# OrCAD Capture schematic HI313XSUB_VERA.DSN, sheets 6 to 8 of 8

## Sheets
6 PAGE7_Hi3130V200: size Custom
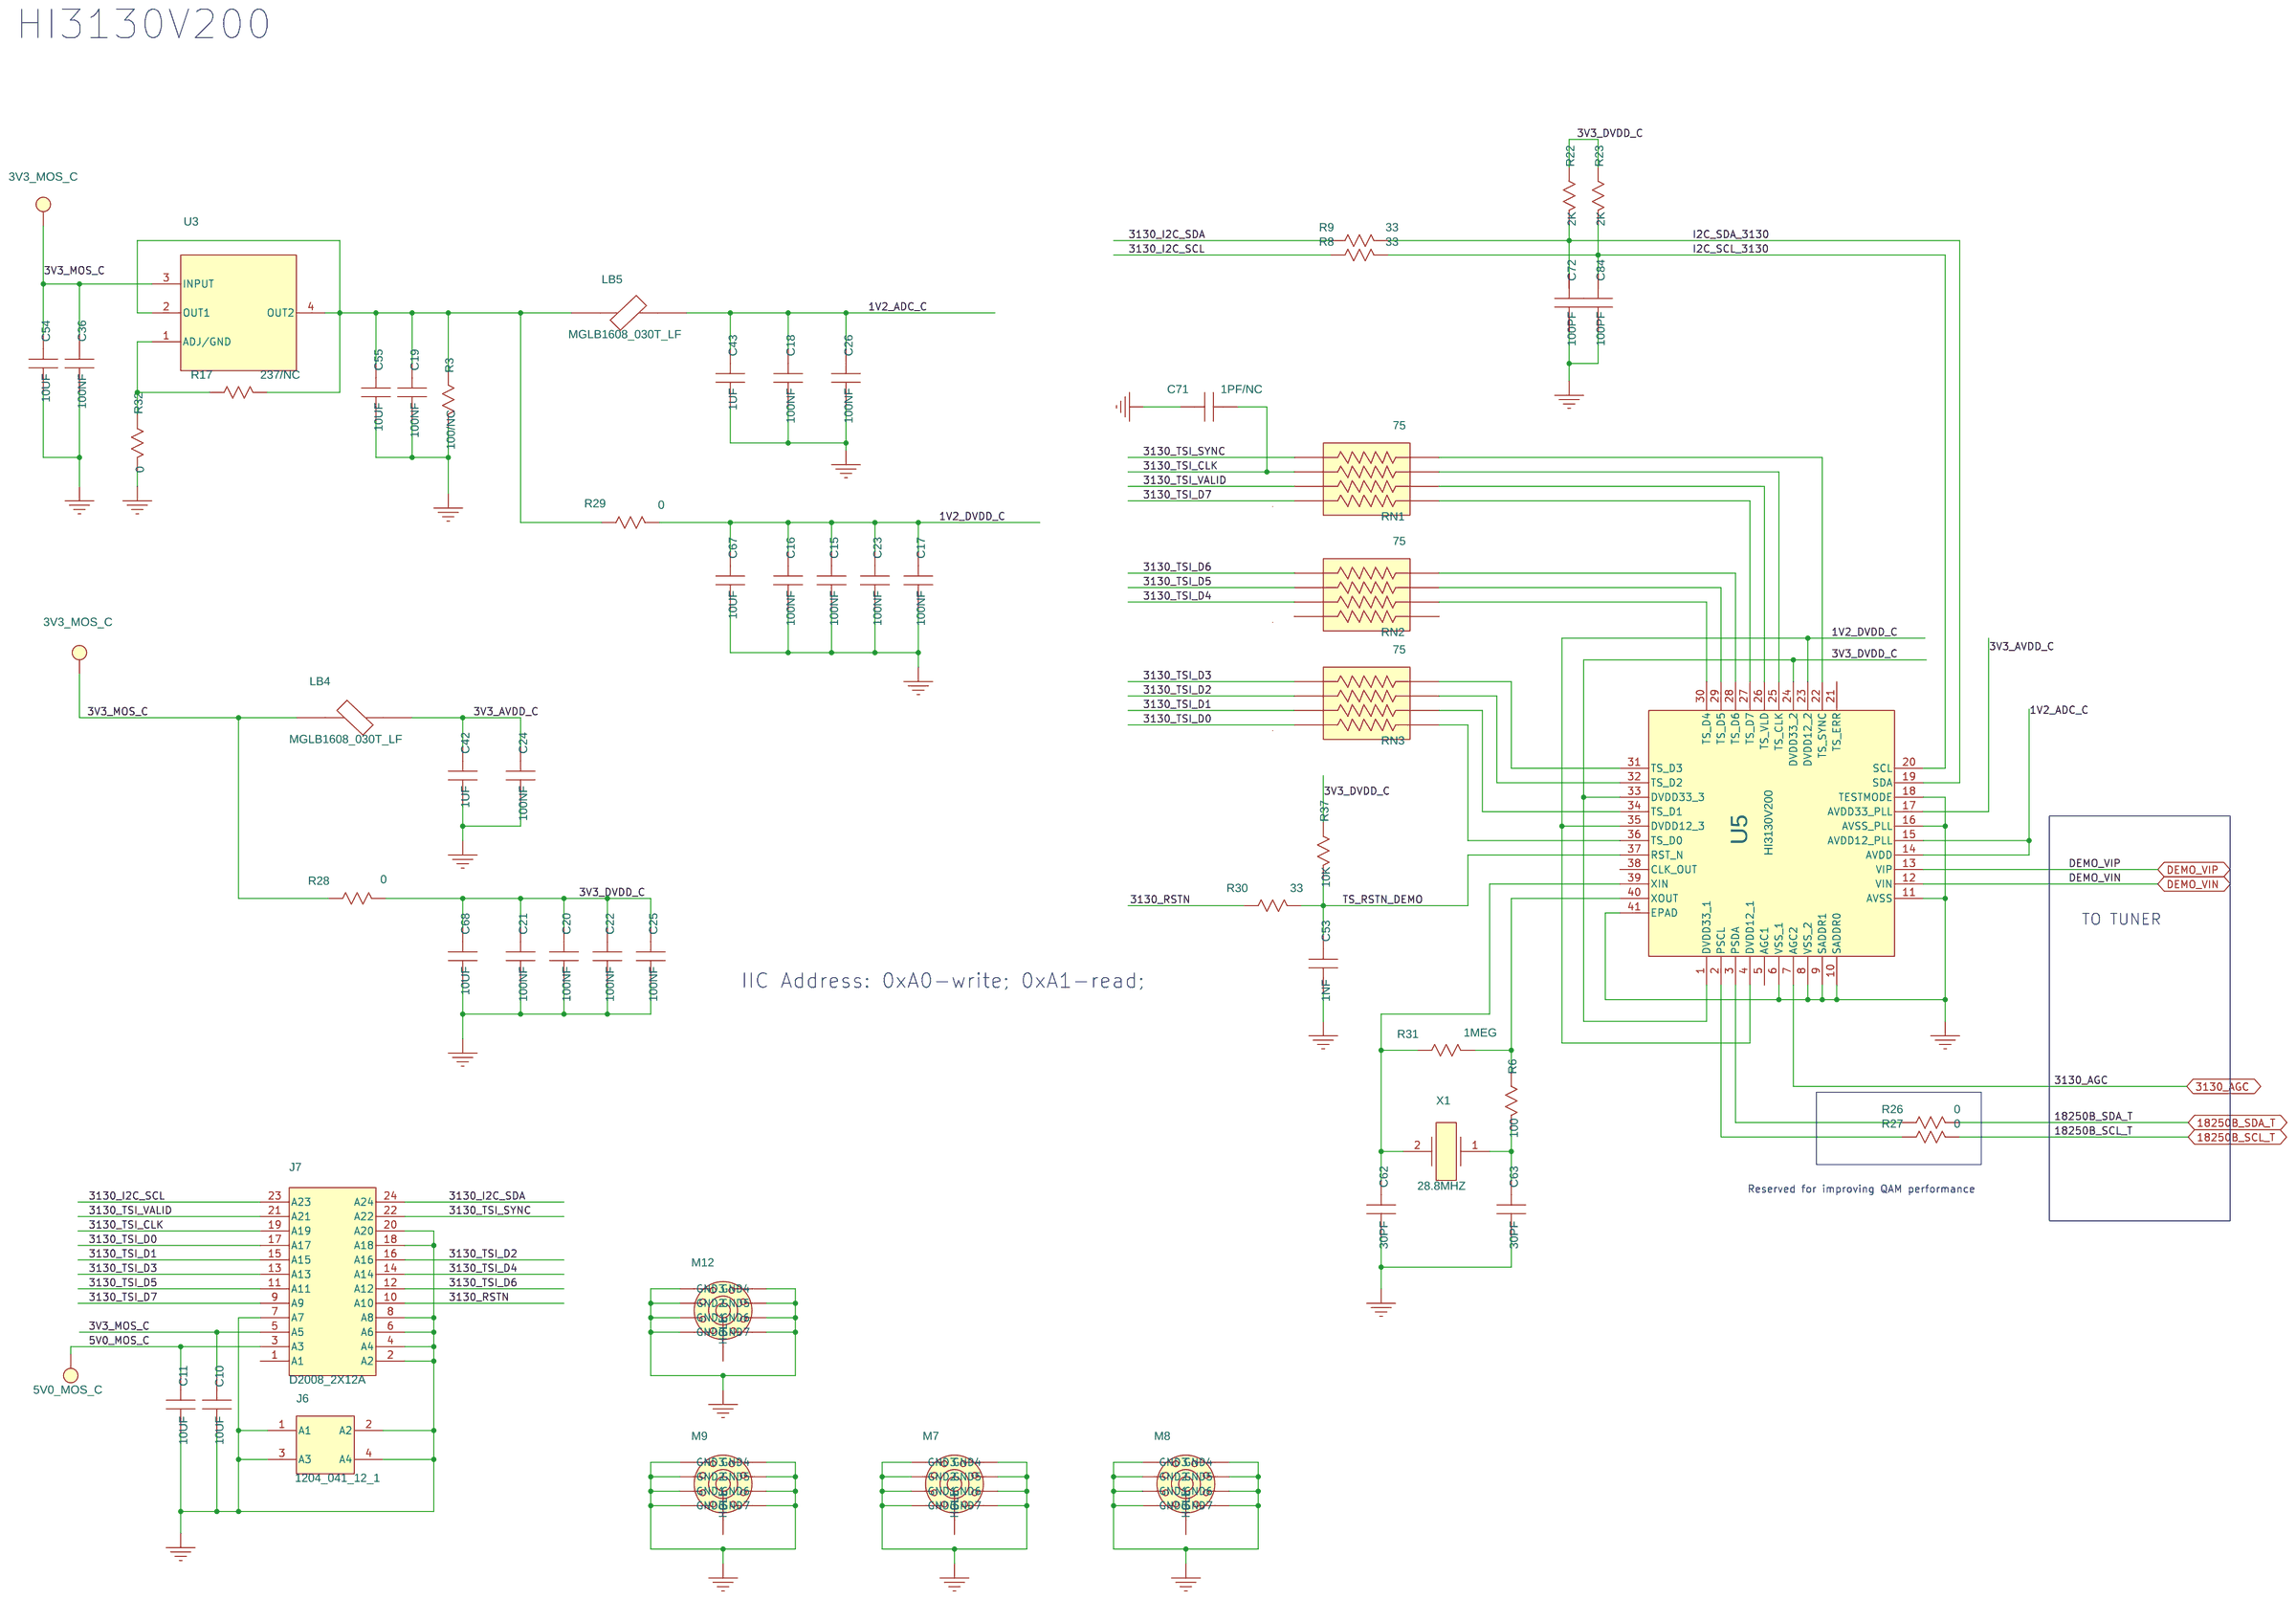
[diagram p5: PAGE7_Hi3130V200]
7 PAGE8_TDA18250B: size Custom
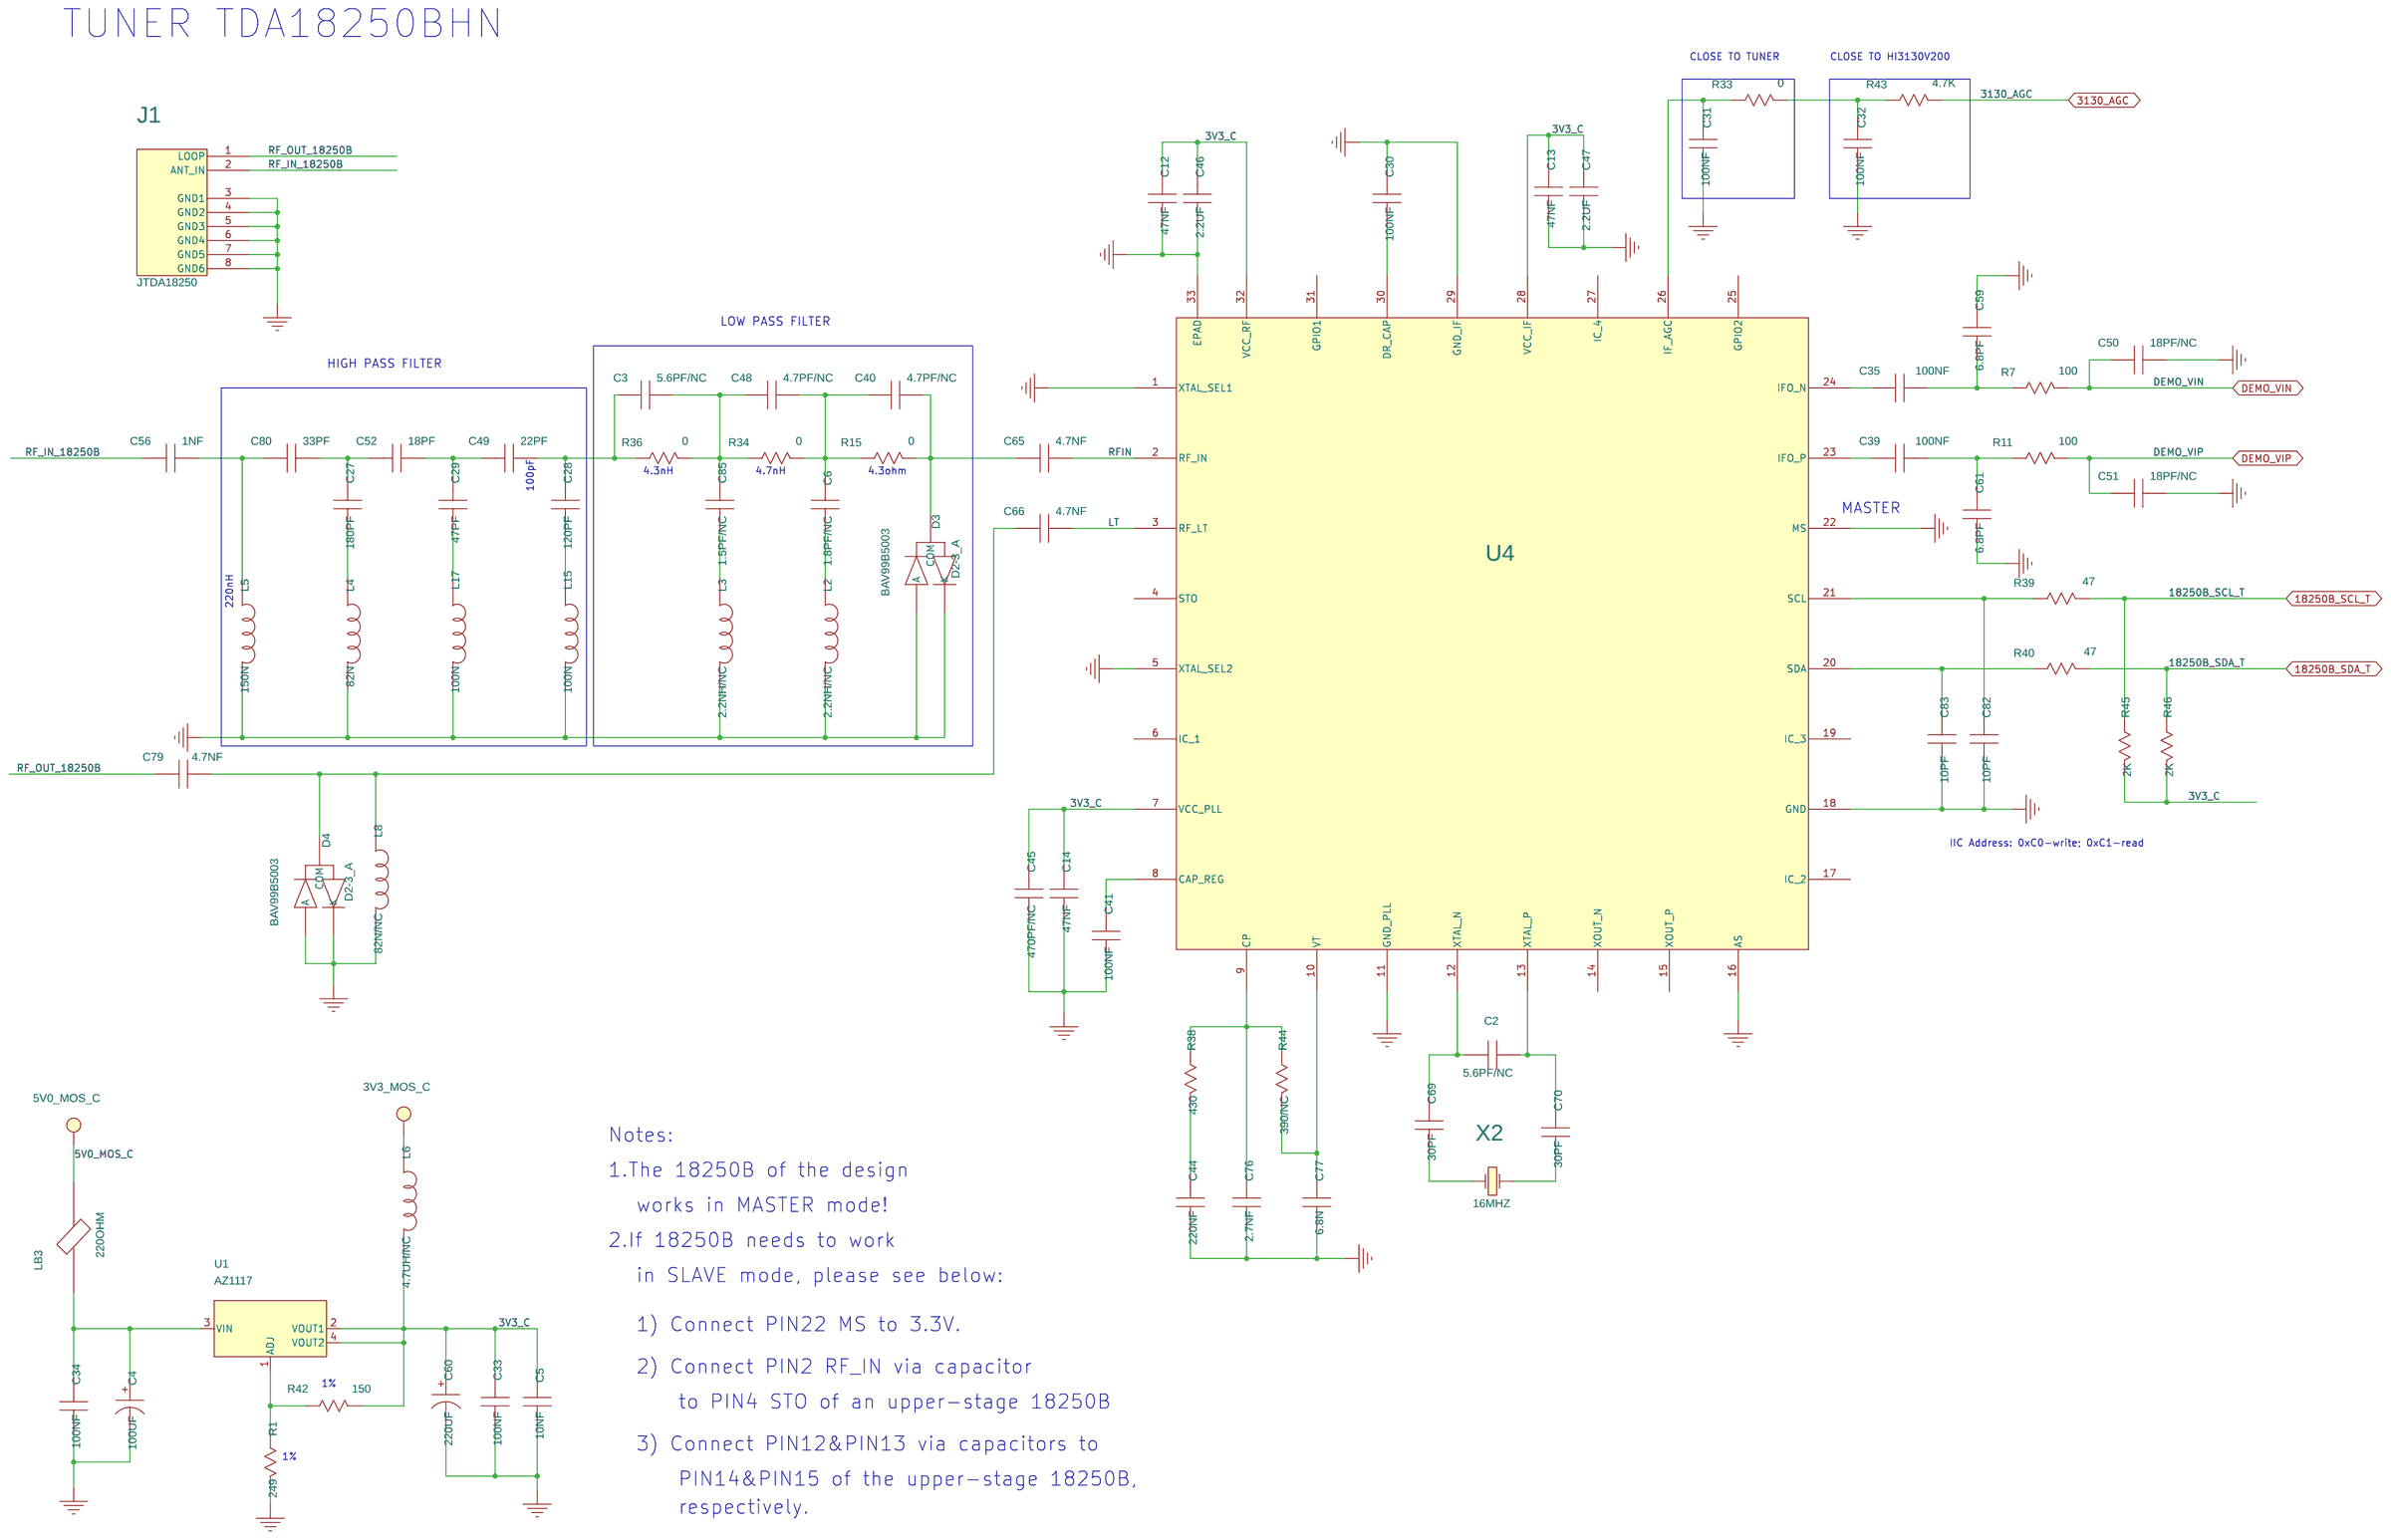
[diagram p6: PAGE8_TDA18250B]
8 PAGE6_MXL603//MXL608: size Custom
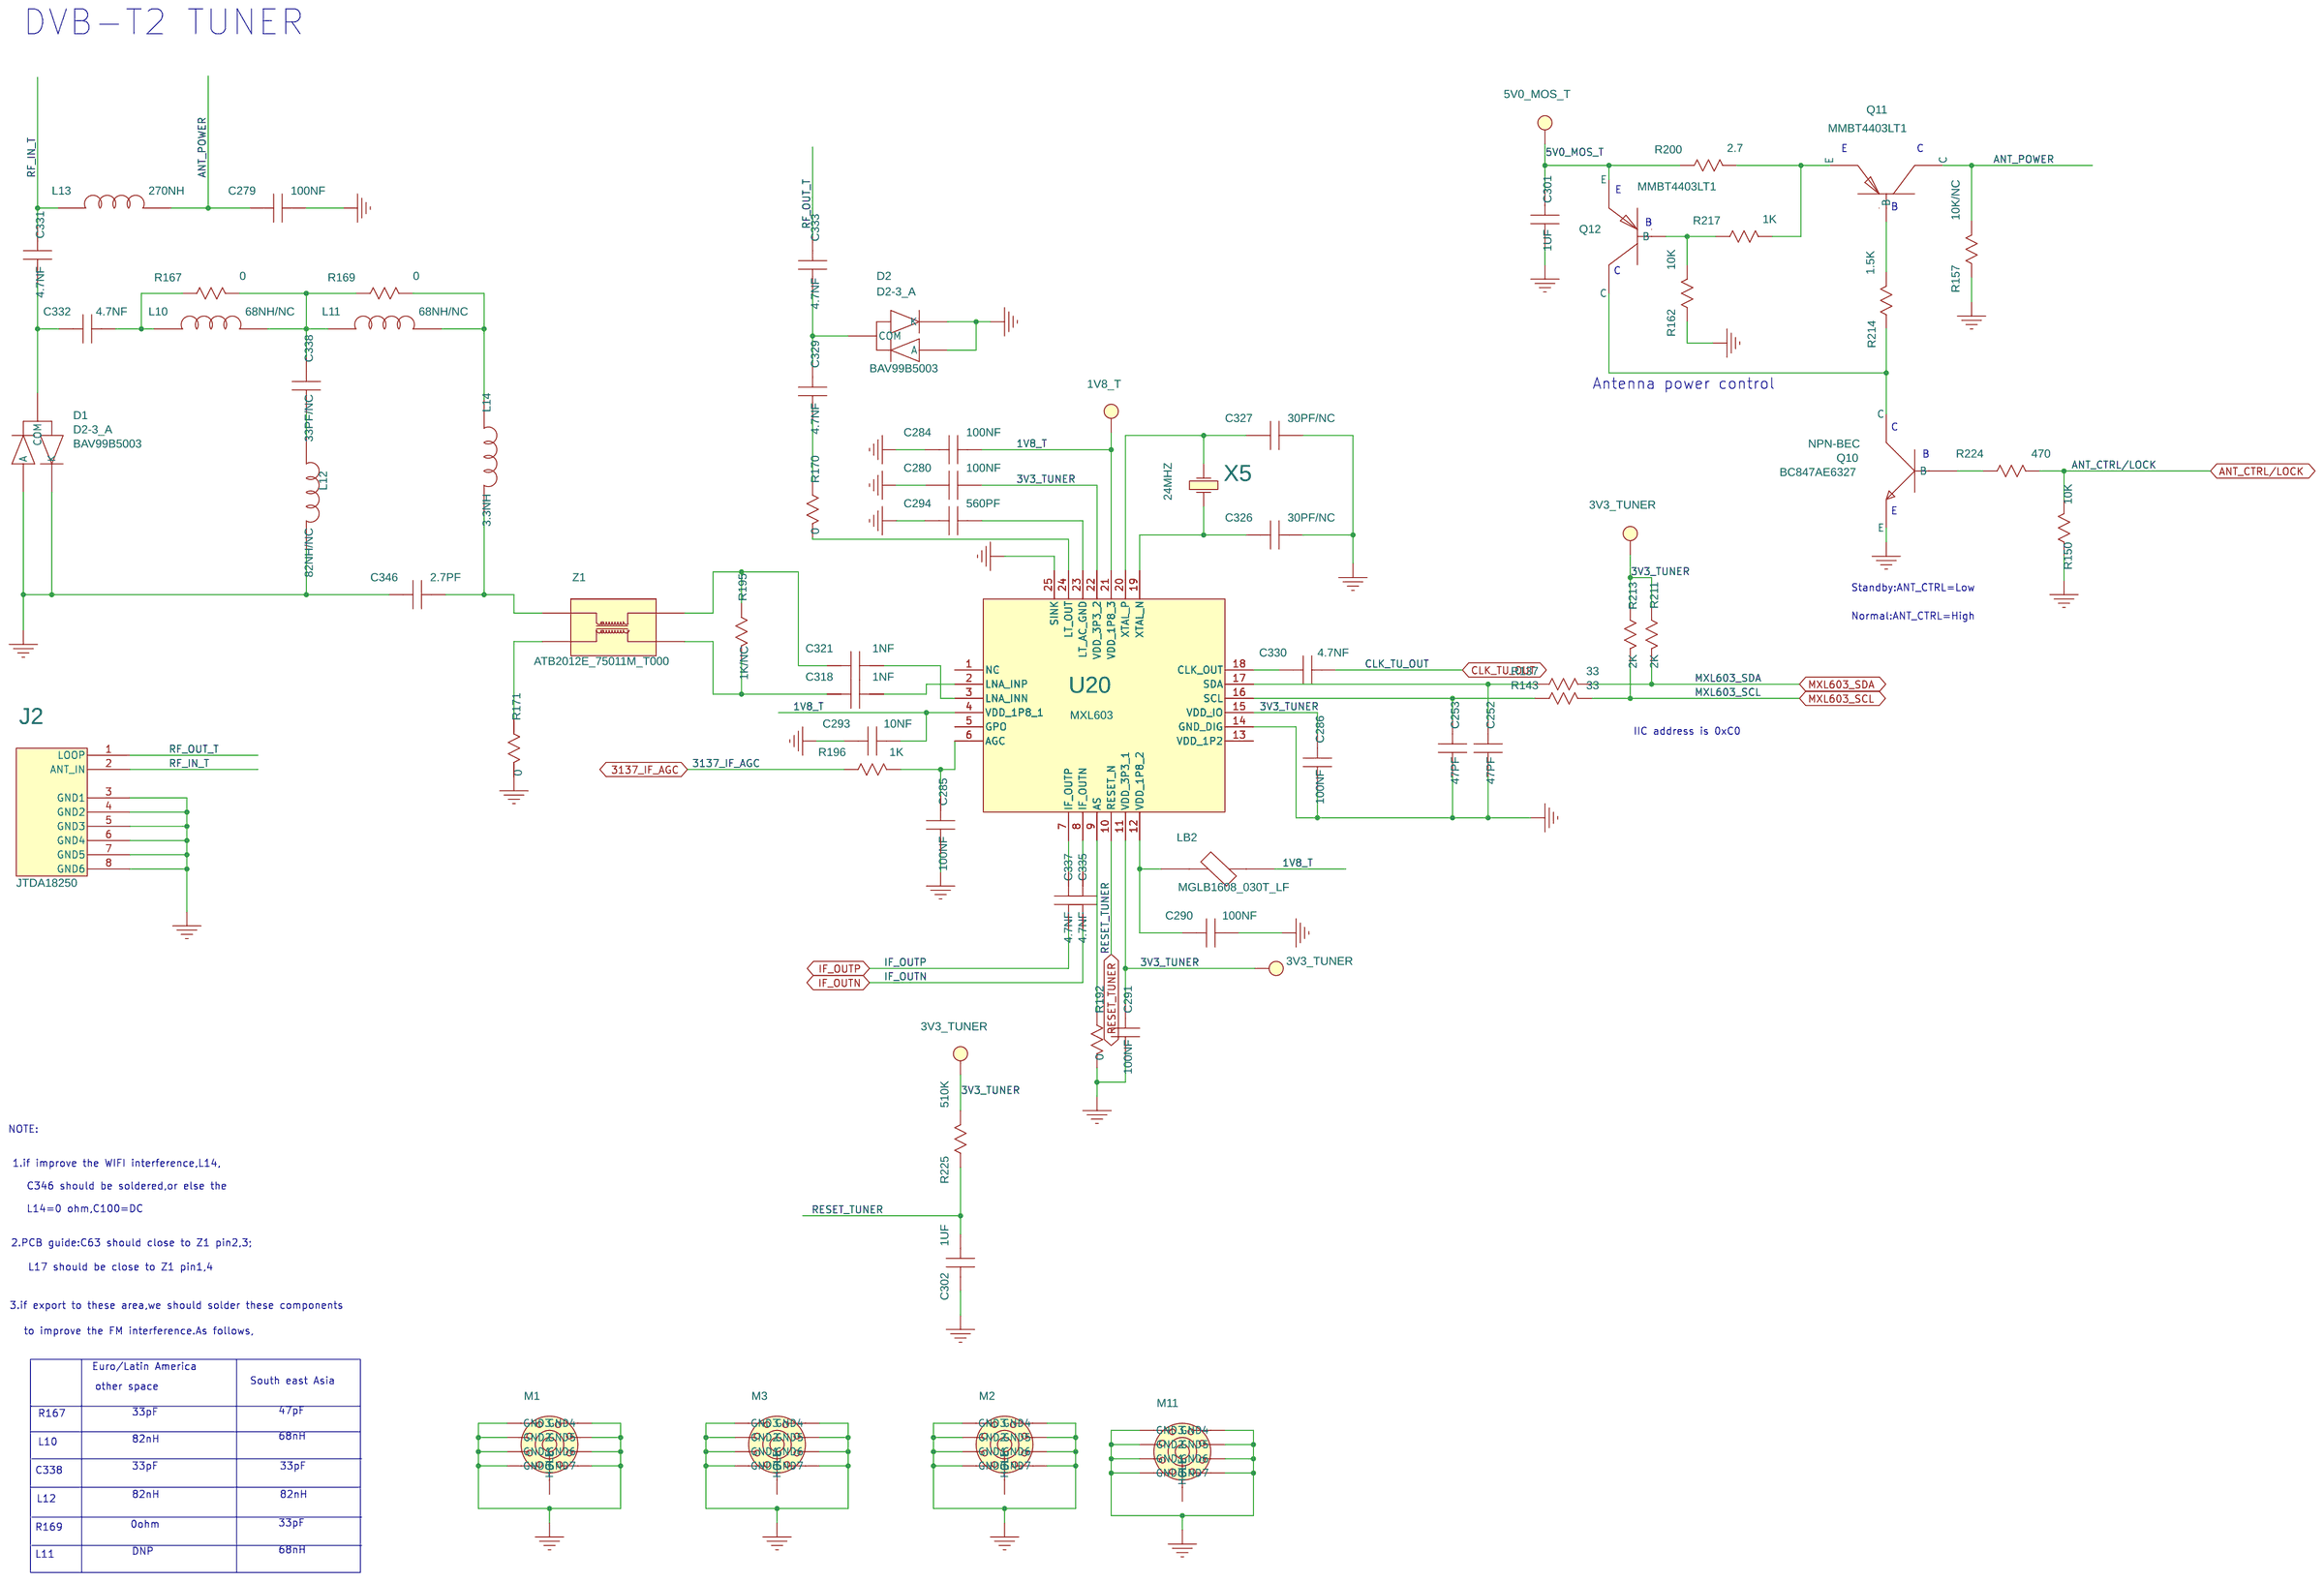
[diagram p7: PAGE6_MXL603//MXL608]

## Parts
sheet PAGE6_MXL603//MXL608
C252  47PF  [SC0402]
C253  47PF  [SC0402]
C279  100NF  [SC0402]
C280  100NF  [SC0402]
C284  100NF  [SC0402]
C285  100NF  [SC0402]
C286  100NF  [SC0402]
C290  100NF  [SC0402]
C291  100NF  [SC0402]
C293  10NF  [SC0402]
C294  560PF  [SC0603]
C301  1UF  [SC0603]
C302  1UF  [SC0603]
C318  1NF  [SC0603]
C321  1NF  [SC0603]
C326  30PF/NC  [SC0402]
C327  30PF/NC  [SC0402]
C329  4.7NF  [SC0402]
C330  4.7NF  [SC0402]
C331  4.7NF  [SC0402]
C332  4.7NF  [SC0402]
C333  4.7NF  [SC0402]
C335  4.7NF  [SC0402]
C337  4.7NF  [SC0402]
C338  33PF/NC  [SC0402]
C346  2.7PF  [SC0402]
D1  D2-3_A  [SOT23]
D2  D2-3_A  [SOT23]
J2  JTDA18250  [JTDA18250]
L10  68NH/NC  [SL0402]
L11  68NH/NC  [SL0402]
L12  82NH/NC  [SL0402]
L13  270NH  [SL0603A]
L14  3.3NH  [SL0402]
LB2  LB  [SL0603]
M1  HOLE-8STARS  [HOLE138-8STAR]
M2  HOLE-8STARS  [HOLE138-8STAR]
M3  HOLE-8STARS  [HOLE138-8STAR]
M11  HOLE-8STARS  [HOLE138-8STAR]
Q10  NPN-BEC  [SOT23]
Q11  PNP-BEC  [SOT23]
Q12  PNP-BEC  [SOT23]
R137  33  [SR0402]
R143  33  [SR0402]
R150  10K  [SR0603]
R157  10K/NC  [SR0603]
R162  10K  [SR0603]
R167  0  [SR0402]
R169  0  [SR0402]
R170  0  [SR0402]
R171  0  [SR0402]
R192  0  [SR0402]
R195  1K/NC  [SR0402]
R196  1K  [SR0402]
R200  2.7  [SR1206]
R211  2K  [SR0402]
R213  2K  [SR0402]
R214  1.5K  [SR0603]
R217  1K  [SR0603]
R224  470  [SR0603]
R225  510K  [SR0603]
U20  MXL603  [MLF24B-050-0404L]
X5  24MHZ  [SX2-1205]
Z1  TCM1005-900-2P-T  [RF4-TDK-ATB2012E]
sheet PAGE7_Hi3130V200
C10  10UF  [SC0805]
C11  10UF  [SC0805]
C15  100NF  [SC0402]
C16  100NF  [SC0402]
C17  100NF  [SC0402]
C18  100NF  [SC0402]
C19  100NF  [SC0402]
C20  100NF  [SC0402]
C21  100NF  [SC0402]
C22  100NF  [SC0402]
C23  100NF  [SC0402]
C24  100NF  [SC0402]
C25  100NF  [SC0402]
C26  100NF  [SC0402]
C36  100NF  [SC0603]
C42  1UF  [SC0603]
C43  1UF  [SC0603]
C53  1NF  [SC0402]
C54  10UF  [SC0805]
C55  10UF  [SC0805]
C62  30PF  [SC0402]
C63  30PF  [SC0402]
C67  10UF  [SC0603]
C68  10UF  [SC0603]
C71  1PF/NC  [SC0402]
C72  100PF  [SC0402]
C84  100PF  [SC0402]
J6  HEAD2X2  [HEAD0202-RM]
J7  WBC2X12  [HEAD0212-RM-SUB]
LB4  LB  [SL0603]
LB5  LB  [SL0603]
M7  HOLE-8STARS  [HOLE138-8STAR]
M8  HOLE-8STARS  [HOLE138-8STAR]
M9  HOLE-8STARS  [HOLE138-8STAR]
M12  HOLE-8STARS  [HOLE138-8STAR]
R3  100/NC  [SR0402]
R6  100  [SR0402]
R8  33  [SR0402]
R9  33  [SR0402]
R17  237/NC  [SR0402]
R22  2K  [SR0402]
R23  2K  [SR0402]
R26  0  [SR0603]
R27  0  [SR0603]
R28  0  [SR0603]
R29  0  [SR0603]
R30  33  [SR0402]
R31  1MEG  [SR0402]
R32  0  [SR0402]
R37  10K  [SR0402]
RN1  75  [SRN8-0804]
RN2  75  [SRN8-0804]
RN3  75  [SRN8-0804]
U3  TLV1117CKTPR  [SOT223A]
U5  HI3130V200  [MLF40B-040-0505L]
X1  28.8MHZ  [XTAL2-200A]
sheet PAGE8_TDA18250B
C2  5.6PF/NC  [SC0402]
C3  5.6PF/NC  [SC0402]
C4  100UF  [CAPC2-79-217]
C5  10NF  [HSC0402]
C6  1.8PF/NC  [SC0402]
C12  47NF  [SC0402]
C13  47NF  [SC0402]
C14  47NF  [SC0402]
C27  180PF  [SC0402]
C28  120PF  [SC0402]
C29  47PF  [SC0402]
C30  100NF  [SC0402]
C31  100NF  [SC0402]
C32  100NF  [SC0402]
C33  100NF  [SC0402]
C34  100NF  [SC0402]
C35  100NF  [SC0402]
C39  100NF  [SC0402]
C40  4.7PF/NC  [SC0402]
C41  100NF  [SC0402]
C44  220NF  [SC0402]
C45  470PF/NC  [SC0402]
C46  2.2UF  [SC0603]
C47  2.2UF  [SC0603]
C48  4.7PF/NC  [SC0402]
C49  22PF  [SC0402]
C50  18PF/NC  [SC0402]
C51  18PF/NC  [SC0402]
C52  18PF  [SC0402]
C56  1NF  [SC0402]
C59  6.8PF  [SC0402]
C60  220UF  [CAPC2-100-250]
C61  6.8PF  [SC0402]
C65  4.7NF  [SC0402]
C66  4.7NF  [SC0402]
C69  30PF  [SC0402]
C70  30PF  [SC0402]
C76  2.7NF  [SC0402]
C77  6.8N  [HSC0402-TA]
C79  4.7NF  [SC0402]
C80  33PF  [SC0402]
C82  10PF  [SC0402]
C83  10PF  [SC0402]
C85  1.5PF/NC  [SC0402]
D3  D2-3_A  [SOT23]
D4  D2-3_A  [SOT23]
J1  JTDA18250  [JTDA18250]
L2  2.2NH/NC  [SL0402]
L3  2.2NH/NC  [SL0402]
L4  82N  [HSL0402-TC]
L5  150N  [HSL0402]
L6  4.7UH/NC  [HSL1007]
L8  82N/NC  [HSL0402-TC]
L15  100N  [HSL0402-TC]
L17  100N  [HSL0402-TC]
LB3  220OHM  [SL0805]
R1  249  [SR0603]
R7  100  [SR0402]
R11  100  [SR0402]
R15  0  [SR0402]
R33  0  [SR0402]
R34  0  [SR0402]
R36  0  [SR0402]
R38  430  [SR0402]
R39  47  [SR0402]
R40  47  [SR0402]
R42  150  [SR0402]
R43  4.7K  [SR0402]
R44  390/NC  [SR0402]
R45  2K  [SR0402]
R46  2K  [SR0402]
U1  LM317EMP  [SOT223A]
U4  TDA18250B  [HVQFN32]
X2  16MHZ  [SX2-1205]

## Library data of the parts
C29 C252 C253 = C: %182%%238%%182%%168%%185%%164%%215%%247%%181%%231%%209%%185%(V): 50; %195%%232%%202%%246%: SMD陶瓷电容-50V-0.047NF-+/-5%-NP0-0402; %208%%161%%192%%224%%195%%251%%179%%198%: SMD陶瓷电容; CODE: 8070549; COMPONENT_HIGH_MAX: 0.55MM; DEVICE: C0402C470J5GAC_7867
C279 C280 C284-C286 C290 C291 = C: %182%%238%%182%%168%%185%%164%%215%%247%%181%%231%%209%%185%(V): 10; %195%%232%%202%%246%: SMD陶瓷电容-10V-100NF-+/-10%-X5R-0402; %208%%161%%192%%224%%195%%251%%179%%198%: SMD陶瓷电容; CODE: 8070561; COMPONENT_HIGH_MAX: 0.55MM; DEVICE: C0402C104K8PAC_7867
C293 = C: %182%%238%%182%%168%%185%%164%%215%%247%%181%%231%%209%%185%(V): 16; %195%%232%%202%%246%: SMD陶瓷电容-16V-10NF-+/-10%-X7R-0402-BT,TS16949; %208%%161%%192%%224%%195%%251%%179%%198%: SMD陶瓷电容; CODE: 8070449; COMPONENT_HIGH_MAX: 0.56MM; DEVICE: GRM155R71C103KA01D
C294 = C: %182%%238%%182%%168%%185%%164%%215%%247%%181%%231%%209%%185%(V): 50; %195%%232%%202%%246%: SMD陶瓷电容-50V-0.56NF-+/-5%-NPO-0603; %208%%161%%192%%224%%195%%251%%179%%198%: SMD陶瓷电容; CODE: 8070414; COMPONENT_HIGH_MAX: 0.9MM; DEVICE: CC0603JRNPO9BN561
C301 = C: %182%%238%%182%%168%%185%%164%%215%%247%%181%%231%%209%%185%(V): 6.3; %195%%232%%202%%246%: SMD陶瓷电容-6.3V-1000NF-+/-10%-X5R-0603; %208%%161%%192%%224%%195%%251%%179%%198%: SMD陶瓷电容; CODE: 8070562; DEVICE: CC0603KRX5R5BB105
C302 = C: %182%%238%%182%%168%%185%%164%%215%%247%%181%%231%%209%%185%(V): 6.3; %195%%232%%202%%246%: SMD陶瓷电容-6.3V-1000NF-+/-10%-X5R-0603; %208%%161%%192%%224%%195%%251%%179%%198%: SMD陶瓷电容; CODE: 8070562; COMPONENT_HIGH_MAX: 0.9MM; DEVICE: CC0603KRX5R5BB105
C318 C321 = C: %182%%238%%182%%168%%185%%164%%215%%247%%181%%231%%209%%185%(V): 50; %195%%232%%202%%246%: SMD陶瓷电容-50V-1NF-+/-10%-X7R-0603; %208%%161%%192%%224%%195%%251%%179%%198%: SMD陶瓷电容; CODE: 8070249; COMPONENT_HIGH_MAX: 0.9MM; DEVICE: 06035C102KAT2A
C62 C63 C69 C70 C326 C327 = C: %182%%238%%182%%168%%185%%164%%215%%247%%181%%231%%209%%185%(V): 50; %195%%232%%202%%246%: SMD陶瓷电容-50V-0.03NF-+/-5%-NPO-0402; %208%%161%%192%%224%%195%%251%%179%%198%: SMD陶瓷电容; CODE: 8070604; COMPONENT_HIGH_MAX: 0.55MM; DEVICE: GRM1555C1H300J
C65 C66 C79 C329-C333 C335 C337 = C: %182%%238%%182%%168%%185%%164%%215%%247%%181%%231%%209%%185%(V): 50; %195%%232%%202%%246%: SMD陶瓷电容-50V-4.7NF-+/-10%-X7R-0402; %208%%161%%192%%224%%195%%251%%179%%198%: SMD陶瓷电容; CODE: 8070559; COMPONENT_HIGH_MAX: 0.55MM; DEVICE: UMK105BJ472KV_F
C80 C338 = C: %182%%238%%182%%168%%185%%164%%215%%247%%181%%231%%209%%185%(V): 50; %195%%232%%202%%246%: SMD陶瓷电容-50V-0.033NF-+/-5%-NP0-0402-BT; %208%%161%%192%%224%%195%%251%%179%%198%: SMD陶瓷电容; CODE: 8070547; COMPONENT_HIGH_MAX: 0.55MM; DEVICE: CC0402JRNPO9BN330
C346 = C: %182%%238%%182%%168%%185%%164%%215%%247%%181%%231%%209%%185%(V): 50; %195%%232%%202%%246%: SMD陶瓷电容-50V-0.0027NF-+/-0.25PF-NPO-0402; %208%%161%%192%%224%%195%%251%%179%%198%: SMD陶瓷电容; CODE: 8070590; COMPONENT_HIGH_MAX: 0.55MM; DEVICE: GRM1555C1H2R7CZ01D
D1 D2 = D2-3_A: %195%%232%%202%%246%: 开关二极管-70V-200MA-1.25V-6NS-串联-SOT-23-2 FIT; CODE: 15010042; DEVICE: BAV99B5003
J1 J2 = JTDA18250
L10 L11 = L: %195%%232%%202%%246%: 贴片电感器-0.068UH-5%-1.7OHM-0402; %208%%161%%192%%224%%195%%251%%179%%198%: 贴片电感器; CODE: 10031125; COMPONENT_HIGH_MAX: 0.55MM; DEVICE: MGCI1005T68NJT_LF
L12 = L: %195%%232%%202%%246%: 贴片电感器-0.082UH-5%-1.9OHM-0402; %208%%161%%192%%224%%195%%251%%179%%198%: 贴片电感器; CODE: 10031126; COMPONENT_HIGH_MAX: 0.55MM; DEVICE: LL1005_FH82NJ
L13 = L: %195%%232%%202%%246%: 贴片电感器-0.27UH-2%-2.3OHM-15-0603; %208%%161%%192%%224%%195%%251%%179%%198%: 贴片电感器; CODE: 10031131; COMPONENT_HIGH_MAX: 1.02MM; DEVICE: 0603CS_R27XJLW
L14 = L: %195%%232%%202%%246%: 贴片电感器-0.0033UH-0.3NH-0.19OHM-0402; %208%%161%%192%%224%%195%%251%%179%%198%: 贴片电感器; CODE: 10031117; COMPONENT_HIGH_MAX: 0.55MM; DEVICE: LL1005_FHL3N3S
LB2 LB4 LB5 = LB: %195%%232%%202%%246%: EMI磁珠-30OHM-0.05OHM-0.4A-0603-; %208%%161%%192%%224%%195%%251%%179%%198%: EMI磁珠; CODE: 10070003; COMPONENT_HIGH_MAX: 0.95MM; DEVICE: MGLB1608_030T_LF
M1-M3 M7-M9 M11 M12 = HOLE-8STARS: %195%%232%%202%%246%: M3螺钉(推荐使用)，对应138MIL星月孔，适用于过波峰焊设计。; DEVICE: 138MIL_STAR_HOLE_APPLY_TO_M3
Q10 = NPN-BEC_0: %195%%232%%202%%246%: 三极管-NPN-45V-100MA-225MW-200MV@100MA-SOT-23-180@2MA; %208%%161%%192%%224%%195%%251%%179%%198%: 三极管; CODE: 15050206; DEVICE: BC847AE6327
Q11 Q12 = PNP-BEC_0: %195%%232%%202%%246%: 三极管-PNP-40V-600MA-350MW-750MV@500MA，400MV@150MA-SOT-23-100@150MA; %208%%161%%192%%224%%195%%251%%179%%198%: 三极管; CODE: 15050072; DEVICE: MMBT4403LT1
R30 R137 R143 = R: %182%%238%%182%%168%%185%%166%%194%%202%(W): 0.06; %195%%232%%202%%246%: 片式厚膜电阻器-0.0625W-33OHM-+/-1%-0402; %208%%161%%192%%224%%195%%251%%179%%198%: 片式厚膜电阻器; %215%%232%%214%%181%%212%%202%%208%%237%%198%%171%%178%%238%: +/-1%; CODE: 7090836; COMPONENT_HIGH_MAX: 0.4MM; DEVICE: RC0402FR_0733RL
R150 R157 R162 = R: %182%%238%%182%%168%%185%%166%%194%%202%(W): 0.1; %195%%232%%202%%246%: 片式厚膜电阻器-0.1W-10000OHM-+/-5%-0603-TS16949; %208%%161%%192%%224%%195%%251%%179%%198%: 片式厚膜电阻器; %215%%232%%214%%181%%212%%202%%208%%237%%198%%171%%178%%238%: +/-5%; CODE: 7090247; DEVICE: RC0603JR_0710K
R167 R169 = R: %182%%238%%182%%168%%185%%166%%194%%202%(W): 0.06; %195%%232%%202%%246%: 片式厚膜电阻器-0.0625W-0OHM-< 50MOHM-0402-1A-BT; %208%%161%%192%%224%%195%%251%%179%%198%: 片式厚膜电阻器; %215%%232%%214%%181%%212%%202%%208%%237%%198%%171%%178%%238%: < 50MOHM; CODE: 7090800; COMPONENT_HIGH_MAX: 0.35MM; DEVICE: RC0402JR_070R
R15 R34 R36 R170 R171 R192 = R: %182%%238%%182%%168%%185%%166%%194%%202%(W): 0.06; %195%%232%%202%%246%: 片式厚膜电阻器-0.0625W-0OHM-< 50MOHM-0402-1A-BT; %208%%161%%192%%224%%195%%251%%179%%198%: 片式厚膜电阻器; %215%%232%%214%%181%%212%%202%%208%%237%%198%%171%%178%%238%: < 50MOHM; CODE: 7090800; DEVICE: RC0402JR_070R
R195 R196 = R: %182%%238%%182%%168%%185%%166%%194%%202%(W): 0.06; %195%%232%%202%%246%: 片式厚膜电阻器-0.0625W-1000OHM-+/-5%-0402-BT; %208%%161%%192%%224%%195%%251%%179%%198%: 片式厚膜电阻器; %215%%232%%214%%181%%212%%202%%208%%237%%198%%171%%178%%238%: +/-5%; CODE: 7090809; COMPONENT_HIGH_MAX: 0.4MM; DEVICE: RC0402JR_071KL
R200 = R: %182%%238%%182%%168%%185%%166%%194%%202%(W): 0.25; %195%%232%%202%%246%: 片式厚膜电阻器-0.25W-2.7OHM-+/-1%-1206-BT; %208%%161%%192%%224%%195%%251%%179%%198%: 片式厚膜电阻器; %215%%232%%214%%181%%212%%202%%208%%237%%198%%171%%178%%238%: +/-1%; CODE: 7090724; DEVICE: RC1206FR_072R7
R211 R213 = R: %182%%238%%182%%168%%185%%166%%194%%202%(W): 0.06; %195%%232%%202%%246%: 片式厚膜电阻器-0.0625W-2000OHM-+/-1%-0402-BT; %208%%161%%192%%224%%195%%251%%179%%198%: 片式厚膜电阻器; %215%%232%%214%%181%%212%%202%%208%%237%%198%%171%%178%%238%: +/-1%; CODE: 7091354; COMPONENT_HIGH_MAX: 0.4MM; DEVICE: RC_02W2001FT
R214 = R: %182%%238%%182%%168%%185%%166%%194%%202%(W): 0.1; %195%%232%%202%%246%: 片式厚膜电阻器-0.1W-1500OHM-+/-1%-0603; %208%%161%%192%%224%%195%%251%%179%%198%: 片式厚膜电阻器; %215%%232%%214%%181%%212%%202%%208%%237%%198%%171%%178%%238%: +/-1%; CODE: 7091272; DEVICE: RK73H1JTTD1501F
R217 = R: %182%%238%%182%%168%%185%%166%%194%%202%(W): 0.1; %195%%232%%202%%246%: 片式厚膜电阻器-0.1W-1000OHM-+/-5%-0603-TS16949; %208%%161%%192%%224%%195%%251%%179%%198%: 片式厚膜电阻器; %215%%232%%214%%181%%212%%202%%208%%237%%198%%171%%178%%238%: +/-5%; CODE: 7090277; DEVICE: RC0603JR_071K
R224 = R: %182%%238%%182%%168%%185%%166%%194%%202%(W): 0.1; %195%%232%%202%%246%: 片式厚膜电阻器-0.1W-470OHM-+/-5%-0603; %208%%161%%192%%224%%195%%251%%179%%198%: 片式厚膜电阻器; %215%%232%%214%%181%%212%%202%%208%%237%%198%%171%%178%%238%: +/-5%; CODE: 7090275; DEVICE: RC0603JR_07470R
R225 = R: %182%%238%%182%%168%%185%%166%%194%%202%(W): 0.1; %195%%232%%202%%246%: 片式厚膜电阻器-0.1W-510000OHM-+/-5%-0603; %208%%161%%192%%224%%195%%251%%179%%198%: 片式厚膜电阻器; %215%%232%%214%%181%%212%%202%%208%%237%%198%%171%%178%%238%: +/-5%; CODE: 7090648; COMPONENT_HIGH_MAX: 0.5MM; DEVICE: RC0603JR_07510KL
U20 = MXL603_0
X5 = X3: %195%%232%%202%%246%: 晶体谐振器-24MHZ-20PF-+/-30PPM-40OHM-HC-49S; %208%%161%%192%%224%%195%%251%%179%%198%: 晶体谐振器; CODE: 12020090; COMPONENT_HIGH_MAX: 4.2MM; DEVICE: ESB240000F20D33
Z1 = TCM1005-900-2P-T: %195%%232%%202%%246%: 平衡-不平衡转换器线圈-00742887; CODE: 875124; COMPONENT_HIGH_MAX: 1.1MM; DEVICE: ATB2012E_75011M_T000
C10 C11 = C: %182%%238%%182%%168%%185%%164%%215%%247%%181%%231%%209%%185%(V): 25; %195%%232%%202%%246%: SMD陶瓷电容-25V-10000NF-+/-20%-X5R-0805; %208%%161%%192%%224%%195%%251%%179%%198%: SMD陶瓷电容; CODE: 8071629; COMPONENT_HIGH_MAX: 1.45MM; DEVICE: C2012X5R1E106KT000N1
C15-C18 C20-C26 C33 C34 = C: %182%%238%%182%%168%%185%%164%%215%%247%%181%%231%%209%%185%(V): 16; %195%%232%%202%%246%: SMD陶瓷电容-16V-100NF-+/-10%-X7R-0402-BT; %208%%161%%192%%224%%195%%251%%179%%198%: SMD陶瓷电容; CODE: 8070614; COMPONENT_HIGH_MAX: 0.6MM; DEVICE: RMEMK105BJ104KV_FR
C19 = C: %182%%238%%182%%168%%185%%164%%215%%247%%181%%231%%209%%185%(V): 16; %195%%232%%202%%246%: SMD陶瓷电容-16V-100NF-±10%-X7R-0402; %208%%161%%192%%224%%195%%251%%179%%198%: SMD陶瓷电容; CODE: 8070614; COMPONENT_HIGH_MAX: 0.6MM; DEVICE: RMEMK105BJ104KV_FR
C36 = C: %182%%238%%182%%168%%185%%164%%215%%247%%181%%231%%209%%185%(V): 50; %195%%232%%202%%246%: SMD陶瓷电容-50V-100NF-±10%-X7R-0603; %208%%161%%192%%224%%195%%251%%179%%198%: SMD陶瓷电容; CODE: 8070627; COMPONENT_HIGH_MAX: 0.9MM; DEVICE: C1608X7R1H104KT000N
C42 C43 = C: %182%%238%%182%%168%%185%%164%%215%%247%%181%%231%%209%%185%(V): 10; %195%%232%%202%%246%: SMD陶瓷电容-10V-1000NF-+/-10%-X5R-0603; %208%%161%%192%%224%%195%%251%%179%%198%: SMD陶瓷电容; CODE: 8070600; COMPONENT_HIGH_MAX: 0.9MM; DEVICE: GRM188R61A105KA61D
C53 C56 = C: %182%%238%%182%%168%%185%%164%%215%%247%%181%%231%%209%%185%(V): 50; %195%%232%%202%%246%: SMD陶瓷电容-50V-1NF-+/-10%-X7R-0402-BT; %208%%161%%192%%224%%195%%251%%179%%198%: SMD陶瓷电容; CODE: 8070531; COMPONENT_HIGH_MAX: 0.56MM; DEVICE: 04025C102KAT2A
C54 C55 = C: %182%%238%%182%%168%%185%%164%%215%%247%%181%%231%%209%%185%(V): 6.3; %195%%232%%202%%246%: SMD陶瓷电容-6.3V-10000NF-+/-10%-X5R-0805; %208%%161%%192%%224%%195%%251%%179%%198%: SMD陶瓷电容; CODE: 8070565; COMPONENT_HIGH_MAX: 1.45MM; DEVICE: CEJMK212BJ106KD_T
C67 C68 = C: %182%%238%%182%%168%%185%%164%%215%%247%%181%%231%%209%%185%(V): 6.3; %195%%232%%202%%246%: SMD陶瓷电容-6.3V-10000NF-+/-20%-X5R-0603-BT,TS16949; %208%%161%%192%%224%%195%%251%%179%%198%: SMD陶瓷电容; CODE: 8070649; COMPONENT_HIGH_MAX: 0.9MM; DEVICE: C1608X5R0J106MT0A0E
C71 = C: %182%%238%%182%%168%%185%%164%%215%%247%%181%%231%%209%%185%(V): 50; %195%%232%%202%%246%: SMD陶瓷电容-50V-0.001NF-+/-0.1PF-NPO-0402-BT; %208%%161%%192%%224%%195%%251%%179%%198%: SMD陶瓷电容; CODE: 8070578; COMPONENT_HIGH_MAX: 0.55MM; DEVICE: GRM1555C1H1R0B
C72 C84 = C: %182%%238%%182%%168%%185%%164%%215%%247%%181%%231%%209%%185%(V): 50; %195%%232%%202%%246%: SMD陶瓷电容-50V-0.1NF-±5%-NPO-0402; %208%%161%%192%%224%%195%%251%%179%%198%: SMD陶瓷电容; CODE: 8070450; COMPONENT_HIGH_MAX: 0.55MM; DEVICE: 04025A101JAT2A
J6 = HEAD2X2: %195%%232%%202%%246%: 插针-普通方脚插针-4PIN-双排-弯脚-5.84MM-3.18MM-2.54MM-THT; %208%%161%%192%%224%%195%%251%%179%%198%: 插针; CODE: 14050061; COMPONENT_HIGH_MAX: 5.2MM; DEVICE: 1204_041_12_1
J7 = WBC2X12: %195%%232%%202%%246%: 华为文档 00383947 - 得康（D2008－2×12A） A; CODE: 383947; COMPONENT_HIGH_MAX: 6.7MM; DEVICE: D2008_2X12A
R3 R6 R7 R11 = R: %182%%238%%182%%168%%185%%166%%194%%202%(W): 0.06; %195%%232%%202%%246%: 片式厚膜电阻器-0.0625W-100OHM-+/-5%-0402-BT; %208%%161%%192%%224%%195%%251%%179%%198%: 片式厚膜电阻器; %215%%232%%214%%181%%212%%202%%208%%237%%198%%171%%178%%238%: +/-5%; CODE: 7090807; COMPONENT_HIGH_MAX: 0.4MM; DEVICE: RC0402JR_07100R
R8 R9 = R: %182%%238%%182%%168%%185%%166%%194%%202%(W): 0.06; %195%%232%%202%%246%: 片式厚膜电阻器-0.0625W-33OHM-±1%-0402; %208%%161%%192%%224%%195%%251%%179%%198%: 片式厚膜电阻器; %215%%232%%214%%181%%212%%202%%208%%237%%198%%171%%178%%238%: ±1%; CODE: 7090836; COMPONENT_HIGH_MAX: 0.4MM; DEVICE: RC0402FR_0733RL
R17 = R: %182%%238%%182%%168%%185%%166%%194%%202%(W): 0.06; %195%%232%%202%%246%: 片式厚膜电阻器-0.0625W-237OHM-+/-1%-0402; %208%%161%%192%%224%%195%%251%%179%%198%: 片式厚膜电阻器; %215%%232%%214%%181%%212%%202%%208%%237%%198%%171%%178%%238%: +/-1%; CODE: 7091135; COMPONENT_HIGH_MAX: 0.4MM; DEVICE: RK73H1ETTP2370F
R22 R23 = R: %182%%238%%182%%168%%185%%166%%194%%202%(W): 0.06; %195%%232%%202%%246%: 片式厚膜电阻器-0.0625W-2000OHM-+/-1%-0402; %208%%161%%192%%224%%195%%251%%179%%198%: 片式厚膜电阻器; %215%%232%%214%%181%%212%%202%%208%%237%%198%%171%%178%%238%: +/-1%; CODE: 7091354; COMPONENT_HIGH_MAX: 0.4MM; DEVICE: RC_02W2001FT
R26-R29 = R: %182%%238%%182%%168%%185%%166%%194%%202%(W): 0.1; %195%%232%%202%%246%: 片式厚膜电阻器-0.1W-0OHM-<50MOHM-0603-1A-BT,TS16949; %208%%161%%192%%224%%195%%251%%179%%198%: 片式厚膜电阻器; %215%%232%%214%%181%%212%%202%%208%%237%%198%%171%%178%%238%: <50MOHM; CODE: 7090522; COMPONENT_HIGH_MAX: 0.5MM; DEVICE: RC0603JR_070RL
R31 = R: %182%%238%%182%%168%%185%%166%%194%%202%(W): 0.06; %195%%232%%202%%246%: 片式厚膜电阻器-0.0625W-1000000OHM-+/-1%-0402; %208%%161%%192%%224%%195%%251%%179%%198%: 片式厚膜电阻器; %215%%232%%214%%181%%212%%202%%208%%237%%198%%171%%178%%238%: +/-1%; CODE: 7090857; COMPONENT_HIGH_MAX: 0.4MM; DEVICE: RK73H1ETTP1004F
R32 = R: %182%%238%%182%%168%%185%%166%%194%%202%(W): 0.06; %195%%232%%202%%246%: 片式厚膜电阻器-0.0625W-0OHM-< 50MΩ-0402-1A; %208%%161%%192%%224%%195%%251%%179%%198%: 片式厚膜电阻器; %215%%232%%214%%181%%212%%202%%208%%237%%198%%171%%178%%238%: < 50MΩ; CODE: 7090800; COMPONENT_HIGH_MAX: 0.4MM; DEVICE: RC0402JR_070R
R37 = R: %182%%238%%182%%168%%185%%166%%194%%202%(W): 0.06; %195%%232%%202%%246%: 片式厚膜电阻器-0.0625W-10000OHM-+/-5%-0402-BT; %208%%161%%192%%224%%195%%251%%179%%198%: 片式厚膜电阻器; %215%%232%%214%%181%%212%%202%%208%%237%%198%%171%%178%%238%: +/-5%; CODE: 7090815; COMPONENT_HIGH_MAX: 0.4MM; DEVICE: RC_02W103JT
RN1-RN3 = RND8-4: %195%%232%%202%%246%: 电阻网络-0.0625W-75OHM-4-8 PIN-+/-5%-SMT-独立式-2.0*1.0*0.45-0.5MM; %208%%161%%192%%224%%195%%251%%179%%198%: 电阻网络; %215%%232%%214%%181%%212%%202%%208%%237%%198%%171%%178%%238%: +/-5%; CODE: 7080136; COMPONENT_HIGH_MAX: 0.55MM; DEVICE: CN1E4KTTD750J
U3 = TLV1117CKTPR: %195%%232%%202%%246%: SWITCHING REGULATORS-3V~12V-0.2%-1A-SOT223-SMT-终端专用-终端专用-00478074; CODE: 39110641; COMPONENT_HIGH_MAX: 1.8MM; DEVICE: AZ1117H_ADJTRG1
U5 = HI3130V200
X1 = X: %195%%232%%202%%246%: 晶体谐振器-28.8MHZ-20PF-+/-30PPM-40OHM; %208%%161%%192%%224%%195%%251%%179%%198%: 晶体谐振器; CODE: *
C2 C3 = C: %182%%238%%182%%168%%185%%164%%215%%247%%181%%231%%209%%185%(V): 50; %195%%232%%202%%246%: SMD陶瓷电容-50V-0.0056NF-+/-0.05PF-NPO-0402; %208%%161%%192%%224%%195%%251%%179%%198%: SMD陶瓷电容; CODE: 8071039; COMPONENT_HIGH_MAX: 0.55MM; DEVICE: 04025J5R6ABSTR
C4 = CP_0: %182%%238%%182%%168%%185%%164%%215%%247%%181%%231%%209%%185%(V): 10; %195%%232%%202%%246%: 非固体插装铝电容-10V-100UF-±20%-5*11-2-0.5MM-极性-105DEGC-1000H; %208%%161%%192%%224%%195%%251%%179%%198%: 非固体插装铝电容; CODE: 8010158; COMPONENT_HIGH_MAX: 12.5MM; DEVICE: 10YXA100MT15X11
C5 = C: %182%%238%%182%%168%%185%%164%%215%%247%%181%%231%%209%%185%(V): 50; %195%%232%%202%%246%: SMD陶瓷电容-50V-10NF-10%-X7R-0402-终端专用; %208%%161%%192%%224%%195%%251%%179%%198%: SMD陶瓷电容; CODE: 8070970; COMPONENT_HIGH_MAX: 0.55MM; DEVICE: 0402B103K500CT
C6 = C: %182%%238%%182%%168%%185%%164%%215%%247%%181%%231%%209%%185%(V): 50; %195%%232%%202%%246%: SMD陶瓷电容-50V-0.0018NF-+/-0.25PF-NPO-0402; %208%%161%%192%%224%%195%%251%%179%%198%: SMD陶瓷电容; CODE: 8070602; COMPONENT_HIGH_MAX: 0.55MM; DEVICE: GRM1555C1H1R8CZ01D
C12-C14 = C: %182%%238%%182%%168%%185%%164%%215%%247%%181%%231%%209%%185%(V): 10; %195%%232%%202%%246%: SMD陶瓷电容-10V-47NF-+/-10%-X7R-0402; %208%%161%%192%%224%%195%%251%%179%%198%: SMD陶瓷电容; CODE: 8070583; COMPONENT_HIGH_MAX: 0.55MM; DEVICE: GRM155R71A473K
C27 = C: %182%%238%%182%%168%%185%%164%%215%%247%%181%%231%%209%%185%(V): 50; %195%%232%%202%%246%: SMD陶瓷电容-50V-0.18NF-+/-5%-NPO-0402; %208%%161%%192%%224%%195%%251%%179%%198%: SMD陶瓷电容; CODE: 8070637; COMPONENT_HIGH_MAX: 0.55MM; DEVICE: CC0402JRNPO9BB181
C28 = C: %182%%238%%182%%168%%185%%164%%215%%247%%181%%231%%209%%185%(V): 50; %195%%232%%202%%246%: SMD陶瓷电容-50V-0.12NF-+/-5%-NP0-0402; %208%%161%%192%%224%%195%%251%%179%%198%: SMD陶瓷电容; CODE: 8071001; COMPONENT_HIGH_MAX: 0.55MM; DEVICE: C0402C470J5GAC_7867
C30-C32 C35 C39 C41 = C: %182%%238%%182%%168%%185%%164%%215%%247%%181%%231%%209%%185%(V): 16; %195%%232%%202%%246%: SMD陶瓷电容-16V-100NF-+/-10%-X7R-0402-BT; %208%%161%%192%%224%%195%%251%%179%%198%: SMD陶瓷电容; CODE: 8070614; COMPONENT_HIGH_MAX: 0.55MM; DEVICE: RMEMK105BJ104KV_FR
C40 C48 = C: %182%%238%%182%%168%%185%%164%%215%%247%%181%%231%%209%%185%(V): 50; %195%%232%%202%%246%: SMD陶瓷电容-50V-0.0047NF-+/-0.05PF-NPO-0402; %208%%161%%192%%224%%195%%251%%179%%198%: SMD陶瓷电容; CODE: 8071038; COMPONENT_HIGH_MAX: 0.55MM; DEVICE: 04025J4R7ABSTR
C44 = C: %182%%238%%182%%168%%185%%164%%215%%247%%181%%231%%209%%185%(V): 16; %195%%232%%202%%246%: SMD陶瓷电容-16V-220NF-+/-10%-X7R-0402; %208%%161%%192%%224%%195%%251%%179%%198%: SMD陶瓷电容; CODE: 8070786; COMPONENT_HIGH_MAX: 0.55MM; DEVICE: CL05B224KO5NNNC
C45 = C: %182%%238%%182%%168%%185%%164%%215%%247%%181%%231%%209%%185%(V): 50; %195%%232%%202%%246%: SMD陶瓷电容-50V-0.47NF-+/-5%-NPO-0402; %208%%161%%192%%224%%195%%251%%179%%198%: SMD陶瓷电容; CODE: 8070582; COMPONENT_HIGH_MAX: 0.55MM; DEVICE: GRM1555C1H471JA01D
C46 C47 = C: %182%%238%%182%%168%%185%%164%%215%%247%%181%%231%%209%%185%(V): 10; %195%%232%%202%%246%: SMD陶瓷电容-10V-2200NF-+/-10%-X5R-0603; %208%%161%%192%%224%%195%%251%%179%%198%: SMD陶瓷电容; CODE: 8070573; COMPONENT_HIGH_MAX: 0.9MM; DEVICE: GRM188R61A225KE34D
C49 = C: %182%%238%%182%%168%%185%%164%%215%%247%%181%%231%%209%%185%(V): 50; %195%%232%%202%%246%: SMD陶瓷电容-50V-0.022NF-+/-5%-NP0-0402-BT; %208%%161%%192%%224%%195%%251%%179%%198%: SMD陶瓷电容; CODE: 8070545; COMPONENT_HIGH_MAX: 0.55MM; DEVICE: RMUMK105CG220JV_F
C50-C52 = C: %182%%238%%182%%168%%185%%164%%215%%247%%181%%231%%209%%185%(V): 50; %195%%232%%202%%246%: SMD陶瓷电容-50V-0.018NF-+/-5%-NPO-0402; %208%%161%%192%%224%%195%%251%%179%%198%: SMD陶瓷电容; CODE: 8070580; COMPONENT_HIGH_MAX: 0.55MM; DEVICE: C0402C180J5GAC_7867
C59 C61 = C: %182%%238%%182%%168%%185%%164%%215%%247%%181%%231%%209%%185%(V): 50; %195%%232%%202%%246%: SMD陶瓷电容-50V-0.0068NF-+/-0.25PF-NP0-0402; %208%%161%%192%%224%%195%%251%%179%%198%: SMD陶瓷电容; CODE: 8070532; COMPONENT_HIGH_MAX: 0.56MM; DEVICE: C0402C689C5GAC_7867
C60 = CP_0: %182%%238%%182%%168%%185%%164%%215%%247%%181%%231%%209%%185%(V): 16; %195%%232%%202%%246%: 非固体插装铝电容-16V-220UF-±20%-6.3*11-2.5-0.5MM-极性-105DEGC-1000H; %208%%161%%192%%224%%195%%251%%179%%198%: 非固体插装铝电容; CODE: 8010290; DEVICE: UVZ1C221MED1TD
C76 = C: %182%%238%%182%%168%%185%%164%%215%%247%%181%%231%%209%%185%(V): 50; %195%%232%%202%%246%: SMD陶瓷电容-50V-2.7NF-+/-10%-X7R-0402; %208%%161%%192%%224%%195%%251%%179%%198%: SMD陶瓷电容; CODE: 8070558; COMPONENT_HIGH_MAX: 0.55MM; DEVICE: C0402C272K5RAC_7867
C77 = C: %195%%232%%202%%246%: SMD陶瓷电容-25V-6.8NF-+/-10%-X7R-0402-终端专用; CODE: 8070670; DEVICE: C1005X7R1H682KT000F
C82 C83 = C: %182%%238%%182%%168%%185%%164%%215%%247%%181%%231%%209%%185%(V): 50; %195%%232%%202%%246%: SMD陶瓷电容-50V-0.01NF-+/-5%-NP0-0402-BT; %208%%161%%192%%224%%195%%251%%179%%198%: SMD陶瓷电容; CODE: 8070530; COMPONENT_HIGH_MAX: 0.56MM; DEVICE: 04025A100JAT2A
C85 = C: %182%%238%%182%%168%%185%%164%%215%%247%%181%%231%%209%%185%(V): 50; %195%%232%%202%%246%: SMD陶瓷电容-50V-0.0015NF-+/-0.1PF-NP0-0402-高Q电容; %208%%161%%192%%224%%195%%251%%179%%198%: SMD陶瓷电容; CODE: 8071238; COMPONENT_HIGH_MAX: 0.6MM; DEVICE: 500SHL1R5BSE
D3 D4 = D2-3_A: %195%%232%%202%%246%: 开关二极管-70V-200MA-1.25V-6NS-串联-SOT-23-2 FIT; %208%%161%%192%%224%%195%%251%%179%%198%: 开关二极管; CODE: 15010042; COMPONENT_HIGH_MAX: 1.26MM; DEVICE: BAV99B5003
L2 L3 = L: %195%%232%%202%%246%: 贴片电感器-0.0022UH-0.3NH-0.16OHM-0.3A-0402; %208%%161%%192%%224%%195%%251%%179%%198%: 贴片电感器; CODE: 10031078; COMPONENT_HIGH_MAX: 0.55MM; DEVICE: MGCI1005T2N2ST_LF
L4 L8 = L: %195%%232%%202%%246%: 终端专用电感磁珠-片式电感-0.082UH-±5%-0.1A-1.9OHM-0402-叠层电感-手机专用; CODE: 10100044; COMPONENT_HIGH_MAX: 0.55MM; DEVICE: HK100582NJ
L5 = L: %195%%232%%202%%246%: 终端片式电感-0.15UH-+/-5%-0.1A-3.2OHM-1.0*0.5*0.5MM-终端专用; %208%%161%%192%%224%%195%%251%%179%%198%: 终端片式电感; CODE: 10100279; COMPONENT_HIGH_MAX: 0.55MM; DEVICE: HK100582NJ
L6 = L: %195%%232%%202%%246%: 贴片电感器-4.7UH-20%-0.26OHM-0.43A-20DEGC-2.5*1.8MM-; %208%%161%%192%%224%%195%%251%%179%%198%: 贴片电感器; CODE: 10031116; COMPONENT_HIGH_MAX: 2MM; DEVICE: LQLBC2518T4R7M
L15 L17 = L: %195%%232%%202%%246%: 终端专用电感磁珠-0.1UH-±5%-0.15A-1.6OHM-0402-叠层电感-手机专用; CODE: 10100004; COMPONENT_HIGH_MAX: 0.6MM; DEVICE: LQG15HNR10J02
LB3 = LB: %208%%161%%192%%224%%195%%251%%179%%198%: EMI磁珠; CODE: 10070012; COMPONENT_HIGH_MAX: 1.05MM; DEVICE: 220
R1 = R: %182%%238%%182%%168%%185%%166%%194%%202%(W): 0.1; %195%%232%%202%%246%: 片式厚膜电阻器-0.1W-249OHM-±1%-0603; %208%%161%%192%%224%%195%%251%%179%%198%: 片式厚膜电阻器; %215%%232%%214%%181%%212%%202%%208%%237%%198%%171%%178%%238%: ±1%; CODE: 7090640; DEVICE: RHS_03K2490FT
R33 = R: %182%%238%%182%%168%%185%%166%%194%%202%(W): 0.06; %195%%232%%202%%246%: 片式厚膜电阻器-0.0625W-0OHM-< 50MOHM-0402-1A-BT; %208%%161%%192%%224%%195%%251%%179%%198%: 片式厚膜电阻器; %215%%232%%214%%181%%212%%202%%208%%237%%198%%171%%178%%238%: < 50MOHM; CODE: 7090800; COMPONENT_HIGH_MAX: 0.4MM; DEVICE: RC0402JR_070R
R38 = R: %182%%238%%182%%168%%185%%166%%194%%202%(W): 0.06; %195%%232%%202%%246%: 片式厚膜电阻器-0.0625W-430OHM-+/-5%-0402; %208%%161%%192%%224%%195%%251%%179%%198%: 片式厚膜电阻器; %215%%232%%214%%181%%212%%202%%208%%237%%198%%171%%178%%238%: +/-5%; CODE: 7090842; COMPONENT_HIGH_MAX: 0.4MM; DEVICE: RK73B1ETTP431J
R39 R40 = R: %182%%238%%182%%168%%185%%166%%194%%202%(W): 0.06; %195%%232%%202%%246%: 片式厚膜电阻器-0.0625W-47OHM-+/-5%-0402; %208%%161%%192%%224%%195%%251%%179%%198%: 片式厚膜电阻器; %215%%232%%214%%181%%212%%202%%208%%237%%198%%171%%178%%238%: +/-5%; CODE: 7090805; COMPONENT_HIGH_MAX: 0.4MM; DEVICE: RC0402JR_0747RL
R42 = R: %182%%238%%182%%168%%185%%166%%194%%202%(W): 0.06; %195%%232%%202%%246%: 片式厚膜电阻器-0.0625W-150OHM-+/-1%-0402--供电专用 07091327-供电专用; %208%%161%%192%%224%%195%%251%%179%%198%: 片式厚膜电阻器; %215%%232%%214%%181%%212%%202%%208%%237%%198%%171%%178%%238%: +/-1%; CODE: 7091730; COMPONENT_HIGH_MAX: 0.4MM; DEVICE: RC0402FR_07150RL
R43 = R: %182%%238%%182%%168%%185%%166%%194%%202%(W): 0.06; %195%%232%%202%%246%: 片式厚膜电阻器-0.0625W-4700OHM-+/-5%-0402-BT; %208%%161%%192%%224%%195%%251%%179%%198%: 片式厚膜电阻器; %215%%232%%214%%181%%212%%202%%208%%237%%198%%171%%178%%238%: +/-5%; CODE: 7090793; COMPONENT_HIGH_MAX: 0.4MM; DEVICE: RK73B1ELTP472J
R44 = R: %182%%238%%182%%168%%185%%166%%194%%202%(W): 0.06; %195%%232%%202%%246%: 片式厚膜电阻器-0.0625W-390OHM-+/-5%-0402; %208%%161%%192%%224%%195%%251%%179%%198%: 片式厚膜电阻器; %215%%232%%214%%181%%212%%202%%208%%237%%198%%171%%178%%238%: +/-5%; CODE: *; COMPONENT_HIGH_MAX: 0.4MM; DEVICE: RK73B1ETTP391J
R45 R46 = R: %182%%238%%182%%168%%185%%166%%194%%202%(W): 0.06; %195%%232%%202%%246%: 片式厚膜电阻器-0.0625W-2000OHM-+/-1%-0402--供电专用-07091354-供电专用; %208%%161%%192%%224%%195%%251%%179%%198%: 片式厚膜电阻器; %215%%232%%214%%181%%212%%202%%208%%237%%198%%171%%178%%238%: +/-1%; CODE: 7091529; COMPONENT_HIGH_MAX: 0.32MM; DEVICE: RC0402FR_072KL
U1 = LM317EMP_0: %195%%232%%202%%246%: VOLTAGE REGULATOR-1.23~37V-0-1A-SOT-223; %208%%161%%192%%224%%195%%251%%179%%198%: VOLTAGE REGULATOR; CODE: 99051CGJ; COMPONENT_HIGH_MAX: 1.8MM; DEVICE: AZ1117
U4 = TDA18250B
X2 = X3: %195%%232%%202%%246%: 晶体谐振器-16MHZ-20PF-+/-30PPM-40OHM-49SMD; %208%%161%%192%%224%%195%%251%%179%%198%: 晶体谐振器; CODE: 12020097; COMPONENT_HIGH_MAX: 4.2MM; DEVICE: ESB160000F20E33

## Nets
1V2_ADC_C: C18.1(A) C26.1(A) C43.1(A) LB5.1 U5.14(AVDD) U5.15(AVDD12_PLL)
1V2_DVDD_C: C15.1(A) C16.1(A) C17.1(A) C23.1(A) C67.1(A) R29.2(B) U5.4(DVDD12_1) U5.23(DVDD12_2) U5.35(DVDD12_3)
1V8_T: C284.2(B) C293.2(B) LB2.2 U20.4(VDD_1P8_1) U20.21(VDD_1P8_3) ; also on sheet 5
3V3_AVDD_C: C24.1(A) C42.1(A) LB4.2 U5.17(AVDD33_PLL)
3V3_C: C5.1(A) C12.1(A) C13.1(A) C14.1(A) C33.1(A) C45.1(A) C46.1(A) C47.1(A) C60.1 L6.2(B) R42.2(B) R45.2(B) R46.2(B) U1.2(VOUT1) U1.4(VOUT2) U4.7(VCC_PLL) U4.28(VCC_IF) U4.32(VCC_RF)
3V3_DVDD_C: C20.1(A) C21.1(A) C22.1(A) C25.1(A) C68.1(A) R22.1(A) R23.1(A) R28.2(B) R37.1(A) U5.1(DVDD33) U5.24(DVDD33_2) U5.33(DVDD33_3)
3V3_MOS_C: C10.1(A) C36.1(A) C54.1(A) J7.5(A5) L6.1(A) LB4.1 R28.1(A) U3.3(INPUT)
3V3_TUNER: C280.2(B) C286.1(A) C291.1(A) R211.1(A) R213.1(A) R225.1(A) U20.11(VDD_3P3_1) U20.15(VDD_IO) U20.22(VDD_3P3_2) ; also on sheet 5
5V0_MOS_C: C11.1(A) J7.3(A3) LB3.2
5V0_MOS_T: C301.1(A) Q12.2(E) R200.1(A) ; also on sheet 5
GND: C4.2 C5.2(B) C10.2(B) C11.2(B) C12.2(B) C13.2(B) C14.2(B) C15.2(B) C16.2(B) C17.2(B) C18.2(B) C19.2(B) C20.2(B) C21.2(B) C22.2(B) C23.2(B) C24.2(B) C25.2(B) C26.2(B) C30.1(A) C31.2(B) C32.2(B) C33.2(B) C34.2(B) C36.2(B) C41.2(B) C42.2(B) C43.2(B) C44.2(B) C45.2(B) C46.2(B) C47.2(B) C50.2(B) C51.2(B) C53.2(B) C54.2(B) C55.2(B) C59.1(A) C60.2 C61.2(B) C62.2(B) C63.2(B) C67.2(B) C68.2(B) C71.1(A) C72.2(B) C76.2(B) C77.2(B) C82.2(B) C83.2(B) C84.2(B) C252.2(B) C253.2(B) C279.2(B) C280.1(A) C284.1(A) C285.2(B) C286.2(B) C290.2(B) C291.2(B) C293.1(A) C294.1(A) C301.2(B) C302.2(B) C326.2(B) C327.2(B) C346.1(A) D1.1(A) D1.2(K) D2.1(A) D2.2(K) D3.1(A) D3.2(K) D4.1(A) D4.2(K) J1.3(GND1) J1.4(GND2) J1.5(GND3) J1.6(GND4) J1.7(GND5) J1.8(GND6) J2.3(GND1) J2.4(GND2) J2.5(GND3) J2.6(GND4) J2.7(GND5) J2.8(GND6) J6.1(A1) J6.2(A2) J6.3(A3) J6.4(A4) J7.2(A2) J7.4(A4) J7.6(A6) J7.7(A7) J7.8(A8) J7.18(A18) J7.20(A20) L2.2(B) L3.2(B) L4.2(B) L5.2(B) L8.2(B) L12.2(B) L15.2(B) L17.2(B) M1.1(GND0) M1.2(GND1) M1.3(GND2) M1.4(GND3) M1.5(GND4) M1.6(GND5) M1.7(GND6) M1.8(GND7) M2.1(GND0) M2.2(GND1) M2.3(GND2) M2.4(GND3) M2.5(GND4) M2.6(GND5) M2.7(GND6) M2.8(GND7) M3.1(GND0) M3.2(GND1) M3.3(GND2) M3.4(GND3) M3.5(GND4) M3.6(GND5) M3.7(GND6) M3.8(GND7) M7.1(GND0) M7.2(GND1) M7.3(GND2) M7.4(GND3) M7.5(GND4) M7.6(GND5) M7.7(GND6) M7.8(GND7) M8.1(GND0) M8.2(GND1) M8.3(GND2) M8.4(GND3) M8.5(GND4) M8.6(GND5) M8.7(GND6) M8.8(GND7) M9.1(GND0) M9.2(GND1) M9.3(GND2) M9.4(GND3) M9.5(GND4) M9.6(GND5) M9.7(GND6) M9.8(GND7) M11.1(GND0) M11.2(GND1) M11.3(GND2) M11.4(GND3) M11.5(GND4) M11.6(GND5) M11.7(GND6) M11.8(GND7) M12.1(GND0) M12.2(GND1) M12.3(GND2) M12.4(GND3) M12.5(GND4) M12.6(GND5) M12.7(GND6) M12.8(GND7) Q10.2(E) R1.2(B) R3.2(B) R32.2(B) R150.1(A) R157.1(A) R162.1(A) R171.2(B) R192.2(B) U4.1(XTAL_SEL1) U4.5(XTAL_SEL2) U4.11(GND_PLL) U4.16(AS) U4.18(GND) U4.22(MS) U4.29(GND_IF) U4.33(EPAD) U5.6(VSS_1) U5.8(VSS_2) U5.9(SADDR1) U5.10(SADDR0) U5.11(AVSS) U5.16(AVSS_PLL) U5.18(TESTMODE) U5.41(EPAD) U20.14(GND_DIG) U20.25(SINK) ; also on sheet 3 4 5
3130_AGC: R43.2(B) U5.7(AGC2)
3130_I2C_SCL: J7.23(A23) R8.1(A)
3130_I2C_SDA: J7.24(A24) R9.1(A)
3130_RSTN: J7.10(A10) R30.1(A)
3130_TSI_CLK: C71.2(B) J7.19(A19) RN1.6
3130_TSI_D0: J7.17(A17) RN3.8
3130_TSI_D1: J7.15(A15) RN3.7
3130_TSI_D2: J7.16(A16) RN3.6
3130_TSI_D3: J7.13(A13) RN3.5
3130_TSI_D4: J7.14(A14) RN2.7
3130_TSI_D5: J7.11(A11) RN2.6
3130_TSI_D6: J7.12(A12) RN2.5
3130_TSI_D7: J7.9(A9) RN1.8
3130_TSI_SYNC: J7.22(A22) RN1.5
3130_TSI_VALID: J7.21(A21) RN1.7
3137_IF_AGC: R196.1(A) ; also on sheet 5
18250B_SCL_T: R27.2(B) R39.2(B) R45.1(A)
18250B_SDA_T: R26.2(B) R40.2(B) R46.1(A)
ANT_CTRL/LOCK: R150.2(B) R224.2(B) ; also on sheet 5
ANT_POWER: C279.1(A) L13.2(B) Q11.3(C) R157.2(B)
CLK_TU_OUT: C330.2(B) ; also on sheet 5
DEMO_VIN: C50.1(A) R7.2(B) U5.12(VIN)
DEMO_VIP: C51.1(A) R11.2(B) U5.13(VIP)
I2C_SCL_3130: C84.1(A) R8.2(B) R23.2(B) U5.20(SCL)
I2C_SDA_3130: C72.1(A) R9.2(B) R22.2(B) U5.19(SDA)
IF_OUTN: C335.2(B) ; also on sheet 5
IF_OUTP: C337.2(B) ; also on sheet 5
LT: C66.2(B) U4.3(RF_LT)
MXL603_SCL: R143.2(B) R213.2(B) ; also on sheet 5
MXL603_SDA: R137.2(B) R211.2(B) ; also on sheet 5
RESET_TUNER: C302.1(A) R225.2(B) U20.10(RESET_N) ; also on sheet 5
RF_IN_18250B: C56.1(A) J1.2(ANT_IN)
RF_IN_T: C331.1(A) J2.2(ANT_IN) L13.1(A)
RF_OUT_18250B: C79.1(A) J1.1(LOOP)
RF_OUT_T: C333.1(A) J2.1(LOOP)
RFIN: C65.2(B) U4.2(RF_IN)
TS_RSTN_DEMO: C53.1(A) R30.2(B) R37.2(B) U5.37(RST_N)
N00885: C70.2(B) X2.2
N01117: C2.2(B) C70.1(A) U4.13(XTAL_P)
N01215: C29.2(B) L17.1(A)
N01219: C40.2(B) C65.1(A) D3.3(COM) R15.2(B)
N01279: R1.1(A) R42.1(A) U1.1(ADJ)
N01287: C30.2(B) U4.30(DR_CAP)
N01291: C31.1(A) R33.1(A) U4.26(IF_AGC)
N01301: C32.1(A) R33.2(B) R43.1(A)
N01309: C35.1(A) U4.24(IFO_N)
N01313: C39.1(A) U4.23(IFO_P)
N01317: C35.2(B) C59.2(B) R7.1(A)
N01325: C39.2(B) C61.1(A) R11.1(A)
N01333: C82.1(A) R39.1(A) U4.21(SCL)
N01341: C83.1(A) R40.1(A) U4.20(SDA)
N01349: C69.2(B) X2.1
N01355: C2.1(A) C69.1(A) U4.12(XTAL_N)
N01365: C76.1(A) R38.1(A) R44.1(A) U4.9(CP)
N01379: C44.1(A) R38.2(B)
N01383: C77.1(A) R44.2(B) U4.10(VT)
N01393: C41.1(A) U4.8(CAP_REG)
N01399: C6.2(B) L2.1(A)
N01403: C6.1(A) C40.1(A) C48.2(B) R15.1(A) R34.2(B)
N01417: C85.2(B) L3.1(A)
N01421: C28.2(B) L15.1(A)
N01425: C3.2(B) C48.1(A) C85.1(A) R34.1(A) R36.2(B)
N01439: C3.1(A) C28.1(A) C49.2(B) R36.1(A)
N01453: C27.2(B) L4.1(A)
N01457: C29.1(A) C49.1(A) C52.2(B)
N01465: C27.1(A) C52.1(A) C80.2(B)
N01473: C56.2(B) C80.1(A) L5.1(A)
N01481: C66.1(A) C79.2(B) D4.3(COM) L8.1(A)
N01497: C4.1 C34.1(A) LB3.1 U1.3(VIN)
N02776: RN3.4 U5.31(TS_D3)
N02784: RN3.2 U5.34(TS_D1)
N02792: RN2.3 U5.29(TS_D5)
N02798: RN1.4 U5.22(TS_SYNC)
N02804: RN1.2 U5.26(TS_VLD)
N02826: R27.1(A) U5.2(PSCL)
N02832: R26.1(A) U5.3(PSDA)
N03366: C62.1(A) R31.1(A) U5.39(XIN) X1.2
N03384: RN1.3 U5.25(TS_CLK)
N03390: R17.1(A) R32.1(A) U3.1(ADJ/GND)
N03400: C19.1(A) C55.1(A) LB5.2 R3.1(A) R17.2(B) R29.1(A) U3.2(OUT1) U3.4(OUT2)
N03436: R6.1(A) R31.2(B) U5.40(XOUT)
N03446: C63.1(A) R6.2(B) X1.1
N03454: RN2.2 U5.30(TS_D4)
N03460: RN2.4 U5.28(TS_D6)
N03466: RN1.1 U5.27(TS_D7)
N03472: RN3.3 U5.32(TS_D2)
N03480: RN3.1 U5.36(TS_D0)
N04875: C252.1(A) R137.1(A) U20.17(SDA)
N04997: R170.2(B) U20.24(LT_OUT)
N05295: R192.1(A) U20.9(AS)
N05301: C318.1(A) R195.2(B) Z1.1
N05313: R171.1(A) Z1.4
N05319: C321.1(A) R195.1(A) Z1.2
N05335: C346.2(B) L14.2(B) Z1.3
N05353: C290.1(A) LB2.1 U20.12(VDD_1P8_2)
N05361: C335.1(A) U20.8(IF_OUTN)
N05397: C337.1(A) U20.7(IF_OUTP)
N05405: Q10.3(C) Q12.3(C) R214.1(A)
N05447: C327.1(A) U20.20(XTAL_P) X5.1
N05461: C329.1(A) C333.2(B) D2.3(COM)
N05469: C332.2(B) L10.1(A) R167.1(A)
N05479: C321.2(B) U20.3(LNA_INN)
N05487: C318.2(B) U20.2(LNA_INP)
N05495: C285.1(A) R196.2(B) U20.6(AGC)
N05507: C330.1(A) U20.18(CLK_OUT)
N05511: C294.2(B) U20.23(LT_AC_GND)
N05517: C329.2(B) R170.1(A)
N05521: Q10.1(B) R224.1(A)
N05525: Q11.1(B) R214.2(B)
N05529: C338.2(B) L12.1(A)
N05533: C331.2(B) C332.1(A) D1.3(COM)
N05541: L11.2(B) L14.1(A) R169.2(B)
N05551: C338.1(A) L10.2(B) L11.1(A) R167.2(B) R169.1(A)
N05565: C326.1(A) U20.19(XTAL_N) X5.2
N05575: C253.1(A) R143.1(A) U20.16(SCL)
N05583: Q11.2(E) R200.2(B) R217.2(B)
N05593: Q12.1(B) R162.2(B) R217.1(A)

Not connected (* = marked no-connect by the designer): J7 1(A1); M1 9(HOLE); M2 9(HOLE); M3 9(HOLE); M7 9(HOLE); M8 9(HOLE); M9 9(HOLE); M11 9(HOLE); M12 9(HOLE); RN2 1 8; U4 4(STO) 6(IC_1) 14(XOUT_N) 15(XOUT_P) 17(IC_2) 19(IC_3) 25(GPIO2) 27(IC_4) 31(GPIO1); U5 5(AGC1) 21(TS_ERR) 38(CLK_OUT); U20 1(NC) 5(GPO) 13(VDD_1P2)

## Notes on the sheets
sheet 6
- HI3130V200
- TO TUNER
- IIC Address: 0xA0-write; 0xA1-read;
- Reserved for improving QAM performance
sheet 7
- TUNER TDA18250BHN
- CLOSE TO TUNER
- CLOSE TO HI3130V200
- LOW PASS FILTER
- HIGH PASS FILTER
- 4.3nH
- 4.7nH
- 4.3ohm
- 100pF
- MASTER
- 220nH
- IIC Address: 0xC0-write; 0xC1-read
- Notes:
- 1.The 18250B of the design
- works in MASTER mode!
- 2.If 18250B needs to work
- in SLAVE mode, please see below:
- 1) Connect PIN22 MS to 3.3V.
- 2) Connect PIN2 RF_IN via capacitor
- 1%
- to PIN4 STO of an upper-stage 18250B
- 3) Connect PIN12&PIN13 via capacitors to
- 1%
- PIN14&PIN15 of the upper-stage 18250B,
- respectively.
sheet 8
- DVB-T2 TUNER
- E
- C
- E
- B
- B
- C
- Antenna power control
- C
- B
- E
- Standby:ANT_CTRL=Low
- Normal:ANT_CTRL=High
- IIC address is 0xC0
- NOTE:
- 1.if improve the WIFI interference,L14,
- C346 should be soldered,or else the
- L14=0 ohm,C100=DC
- 2.PCB guide:C63 should close to Z1 pin2,3;
- L17 should be close to Z1 pin1,4
- 3.if export to these area,we should solder these components
- to improve the FM interference.As follows,
- Euro/Latin America
- other space
- South east Asia
- R167
- 33pF
- 47pF
- 68nH
- L10
- 82nH
- C338
- 33pF
- 33pF
- L12
- 82nH
- 82nH
- R169
- 0ohm
- 33pF
- L11
- DNP
- 68nH
